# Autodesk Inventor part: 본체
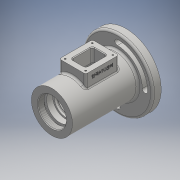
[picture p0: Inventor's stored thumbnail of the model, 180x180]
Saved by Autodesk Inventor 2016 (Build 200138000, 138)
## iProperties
Created: 2017-05
Part Number: 본체
Material: 일반
Document SubType Name: Modeling
Designer: USER
Density: 1 g/cm^3
Appearance: 기본값
Author: USER
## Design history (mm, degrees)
sketch "스케치1"
  geometry: L1 (0, 0)-(0, 31); L2 (0, 31)-(99, 31); L3 (99, 31)-(99, 53); L4 (99, 53)-(112, 53); L5 (112, 53)-(112, 31); L6 (112, 31)-(115, 31); L7 (115, 31)-(115, 0); L8 (115, 0)-(0, 0)
  constraints: 16 end point, 5 perpendicular, 1 horizontal, 1 parallel, 1 point on line, 1 vertical
  dimensions: "d7" = 62 diameter of L2 L8; "d8" = 115 distance between parallel lines of L7 L1; "d9" = 3 distance between parallel lines of L7 L5; "d10" = 13 distance of L3.end L4.end; "d11" = 106 diameter of L4 L8
revolve "회전1" sketch "스케치1" stored, may be unused: angle "d12" = 90 deg
sketch "스케치2"
  geometry: L1 (0, 0)-(0, 21); L2 (0, 21)-(9, 21); L3 (9, 21)-(9, 24); L4 (9, 24)-(12, 24); L5 (12, 24)-(12, 20); L6 (12, 20)-(21, 20); L7 (21, 20)-(21, 17.5); L8 (21, 17.5)-(24.25, 17.5); L9 (24.25, 17.5)-(24.25, 18.5); L10 (24.25, 18.5)-(26, 18.5); L11 (26, 18.5)-(26, 17.5); L12 (26, 17.5)-(36, 17.5); L13 (37, 18.5)-(37, 23); L14 (40, 26)-(72, 26); L15 (75, 23)-(75, 18.5); L16 (76, 17.5)-(85.7, 17.5); L17 (86, 17.2)-(86, 16.5); L18 (86, 16.5)-(88, 16.5); L19 (91, 13.5)-(91, 10); L20 (91, 10)-(93.7, 10); L21 (93.7, 10)-(93.7, 12.2); L22 (94, 12.5)-(101, 12.5); L23 (115, 22)-(115, 0); L24 (115, 0)-(0, 0); L25 (115, -31)-(115, 31) reference; L26 (101, 12.5)-(101.7, 12.904); L27 (101.7, 12.904)-(101.7, 16); L28 (103.891, 18.889)-(115, 22); L29 (75, 18.5)-(76, 17.5); L30 (37, 18.5)-(36, 17.5); A1 r 3 centre (104.7, 16) between (103.891, 18.889) and (101.7, 16); A2 r 0.3 centre (94, 12.2) between (94, 12.5) and (93.7, 12.2); A3 r 3 centre (88, 13.5) between (91, 13.5) and (88, 16.5); A4 r 0.3 centre (85.7, 17.2) between (86, 17.2) and (85.7, 17.5); A5 r 3 centre (72, 23) between (75, 23) and (72, 26); A6 r 3 centre (40, 23) between (40, 26) and (37, 23); 7 further points
  constraints: 58 end point, 19 perpendicular, 16 point on line, 12 point on circle, 12 tangent, 6 centre point, 4 vertical, 3 equal radius, 1 coincident, 1 collinear
  dimensions: "d13" = 42 diameter of L2 L24; "d14" = 48 diameter of L4 L24; "d15" = 40 diameter of L6 L24; "d16" = 35 diameter of L8 L24; "d17" = 37 diameter of L10 L24; "d18" = 1.75 distance of L9.end L10.end; "d19" = 52 diameter of L14 L24; "d20" = 11 distance of L11.end point (37, 17.5); "d21" = 11 distance of point (75, 17.5) point (86, 17.5); "d22" = 33 diameter of L18 L24; "d23" = 20 diameter of L20 L24; "d24" = 25 diameter of L22 L24; "d25" = 2.7 distance of L19.end L20.end; "d26" = 7.3 distance of point (93.7, 12.5) L22.end; "d27" = 0.7 horizontal distance of L26.end L22.end; "d28" = 30 deg angle of L26 L22; "d29" = 44 diameter of L23.start L24; "d30" = 3 radius of A1; "d32" = 3 distance of L3.end L4.end; "d33" = 12 distance between parallel lines of L5 L1; "d34" = 21 distance between parallel lines of L7 L1; "d35" = 26 distance between parallel lines of L1 L11; "d36" = 38 distance of point (37, 26) point (75, 26); "d38" = 32 diameter of L27.end L24; "d39" = 14 distance from line of L25 L22.end; "d40" = 0.3 radius of A2; "d41" = 3 radius of A3; "d42" = 1 distance of L15.end point (75, 17.5); "d43" = 1 distance of L16.start point (75, 17.5) (= d42); "d44" = 1 distance of L13.start point (37, 17.5) (= d42); "d45" = 1 distance of L12.end point (37, 17.5) (= d44)
revolve "회전2" sketch "스케치2" stored, may be unused: angle "d46" = 90 deg
node "작업 평면1"
sketch "스케치3"
  geometry: L1 (-20, 31)-(20, 31); L2 (20, 31)-(20, 81); L3 (20, 81)-(-20, 81); L4 (-20, 81)-(-20, 31); L5 (-20, 56)-(20, 56); L6 (31, 0)-(-31, 0) reference; 2 further points
  constraints: 10 end point, 3 midpoint, 2 parallel, 1 horizontal, 1 perpendicular, 1 vertical alignment
  dimensions: "d48" = 50 distance of L1.end L2.end; "d49" = 56 distance between parallel lines of L6 L5; "d50" = 40 distance of L1.start L1.end
extrude "돌출1" join sketch "스케치3" stored distance "d51" = 10; taper "d52" = 0 deg
sketch "스케치4"
  geometry: L1 (-11, 40)-(11, 40); L2 (11, 40)-(11, 72); L3 (11, 72)-(-11, 72); L4 (-11, 72)-(-11, 40); L5 (-11, 56)-(11, 56); L6 (31, 0)-(-31, 0) reference; 3 further points
  constraints: 10 end point, 4 midpoint, 2 parallel, 1 horizontal, 1 perpendicular, 1 vertical alignment
  dimensions: "d53" = 56 distance between parallel lines of L6 L5; "d54" = 32 distance of L1.end L2.end; "d55" = 22 distance of L1.start L1.end
extrude "돌출2" cut sketch "스케치4" distance "d56" = 44; taper "d57" = 0 deg
sketch "스케치5" dims "d58" = 83
  geometry: L1 (59.452, 0)-(-59.452, 0); L2 (0, -61.922)-(0, 61.922); L3 (0, 0)-(-33.884, -33.884); A1 r 41.5 centre (0, 0) between (0, 41.5) and (-41.5, 0); A2 r 45.5 centre (0, 0) between (0, 45.5) and (-45.5, 0); A3 r 37.5 centre (0, 0) between (0, 37.5) and (-37.5, 0); A4 r 4 centre (0, 41.5) between (0, 37.5) and (0, 45.5); A5 r 4 centre (-41.5, 0) between (-45.5, 0) and (-37.5, 0); A6 r 37.5 centre (0, 0) between (0, -37.5) and (37.5, 0); A7 r 4 centre (0, -41.5) between (0, -37.5) and (0, -45.5); A8 r 45.5 centre (0, 0) between (0, -45.5) and (45.5, 0); A9 r 4 centre (41.5, 0) between (45.5, 0) and (37.5, 0); 2 further points
  constraints: 18 point on circle, 9 centre point, 6 end point, 6 symmetric about line, 4 tangent, 3 coincident, 2 midpoint, 2 point on line, 1 horizontal, 1 vertical, 1 vertical alignment, 6 other
  dimensions: "d59" = 4 radius of A5; "d61" = 45 deg angle of L1 L3
extrude "돌출3" cut sketch "스케치5" stored distance "d62" = 44; taper "d63" = 0 deg
sketch "스케치6"
  geometry: L1 (-11, 72)-(-11, 40) reference; L2 (-11, 56)-(-2.646, 56); 2 further points
  constraints: 2 end point, 1 horizontal, 1 midpoint
  dimensions: "d64" = 15.5 horizontal distance of point (0, 0) point (-15.5, 35.5); "d65" = 20.5 distance from line of L2 point (-15.5, 35.5)
hole "구멍1" sketch "스케치6" at (-15.5, 35.5) diameter "d66" = 2.459; stored, may be unused: countersink angle "d70" = 90 deg, drill point angle "d72" = 118 deg; dims "d67" = 6, "d68" = 4, "d69" = 2, "d71" = 8
feature "스레드1" dims "d79" = 10, "d80" = 0
chamfer "모따기1" distance "d81" = 1; stored, may be unused: second distance "d82" = 2, angle "d83" = 45 deg
fillet "모깎기1" dims "d84" = 3
chamfer "모따기2" distance "d85" = 1; stored, may be unused: second distance "d86" = 2, angle "d87" = 45 deg
fillet "모깎기2" dims "d88" = 3
fillet "모깎기3" dims "d89" = 3
fillet "모깎기4" dims "d90" = 3
fillet "모깎기5" dims "d91" = 3
node "작업 평면2"
sketch "스케치7"
  geometry: L1 (75, -34)-(13, -34) reference; L2 (0, 0)-(0, 44) reference; 2 further points
  constraints: 1 other
  dimensions: "d93" = 56 distance from line of point (8, 22) L1; "d94" = 8 distance from line of point (8, 22) L2
feature "엠보싱1" sketch "스케치7" dims "d95" = 0.5, "d96" = 0
node "솔리드1"
pattern_linear "직사각형 패턴1" dims "d75" = 31, "d78" = 41
other parameters: "d0" = 62, "d47" = 44
